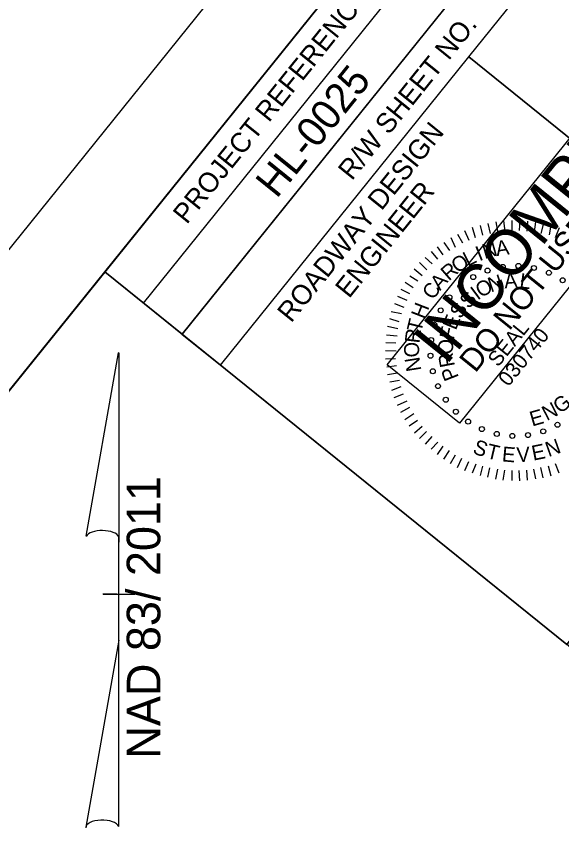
# Model space of a CAD drawing. Extents: x 1487832 to 1490056, y 498345 to 500343.
# Drawn here: x 1488790.9 to 1488928.7, y 500014.9 to 500224.6 of the extents above; entities that cross this region are included whole.
import ezdxf

# ---------------------------------------------------------------- set-up
doc = ezdxf.new("R2010")
doc.units = 0
for name, color, linetype in [('Old_Level_9', 7, 'Continuous'), ('Prop North Arrow NAD83 for Plan Sheets CELL', 7, 'Continuous'), ('Sheet Border Standard 30in CELL', 7, 'Continuous'), ('Sheet Clip Boundary CELL', 7, 'Continuous'), ('Sheet Data Field CELL', 7, 'Continuous'), ('Sheet Plan CELL', 7, 'Continuous'), ('Sheet Plot Border Outside CELL', 7, 'Continuous'), ('Sheet Sticker Incomplete CELL', 7, 'Continuous')]:
    doc.layers.add(name, color=color, linetype=linetype)

msp = doc.modelspace()

# ---------------------------------------------------------------- linework, layer by layer
at = {"layer": 'Old_Level_9'}
for p, q in [((1488910.12, 500172.28), (1488910.67, 500169.78)), ((1488912.13, 500172.71), (1488912.53, 500170.33)), ((1488914.02, 500172.98), (1488914.37, 500170.39)), ((1488916.15, 500173.07), (1488916.2, 500170.58)), ((1488918.21, 500173.07), (1488917.98, 500170.56)), ((1488920.15, 500172.93), (1488919.92, 500170.41)), ((1488922.16, 500172.72), (1488921.79, 500170.19)), ((1488924.19, 500172.36), (1488923.54, 500169.81)), ((1488904.19, 500170.51), (1488905.31, 500168.06)), ((1488906.16, 500171.36), (1488906.93, 500168.81)), ((1488908.18, 500171.79), (1488908.79, 500169.36)), ((1488926.01, 500171.92), (1488925.57, 500169.45)), ((1488928.15, 500171.22), (1488927.14, 500168.7)), ((1488900.75, 500168.79), (1488901.86, 500166.34)), ((1488902.44, 500169.61), (1488903.66, 500167.46)), ((1488897.3, 500166.43), (1488898.73, 500164.37)), ((1488898.96, 500167.53), (1488900.39, 500165.48)), ((1488895.8, 500165.2), (1488897.35, 500163.3)), ((1488892.82, 500162.46), (1488894.66, 500160.59)), ((1488894.25, 500163.75), (1488895.99, 500162.09)), ((1488891.5, 500160.83), (1488893.53, 500159.19)), ((1488890.34, 500159.07), (1488892.4, 500157.79)), ((1488888.14, 500155.7), (1488890.32, 500154.58)), ((1488889.23, 500157.52), (1488891.22, 500156.17)), ((1488887.26, 500153.97), (1488889.65, 500152.95)), ((1488886.53, 500152.11), (1488888.84, 500151.15)), ((1488885.68, 500150.1), (1488888.3, 500149.53)), ((1488885.24, 500148.28), (1488887.59, 500147.53)), ((1488884.73, 500146.37), (1488887.35, 500145.8)), ((1488884.47, 500144.14), (1488887.13, 500143.93)), ((1488884.32, 500142.21), (1488886.82, 500142.12)), ((1488884.25, 500140.21), (1488886.89, 500140.13)), ((1488884.26, 500138.15), (1488886.75, 500138.2)), ((1488884.55, 500136.11), (1488887, 500136.45)), ((1488884.76, 500134.15), (1488887.28, 500134.56)), ((1488885.32, 500132.29), (1488887.75, 500132.76)), ((1488885.82, 500130.21), (1488888.22, 500131.1)), ((1488886.38, 500128.35), (1488888.77, 500129.24)), ((1488887.23, 500126.37), (1488889.67, 500127.49)), ((1488888.13, 500124.62), (1488890.41, 500125.86)), ((1488889.11, 500122.81), (1488891.36, 500124.33)), ((1488890.21, 500121.15), (1488892.32, 500122.65)), ((1488891.53, 500119.44), (1488893.49, 500121.07)), ((1488892.82, 500118.01), (1488894.62, 500119.77)), ((1488894.33, 500116.54), (1488896.04, 500118.5)), ((1488895.74, 500115.27), (1488897.47, 500117.09)), ((1488897.38, 500113.95), (1488898.79, 500116.02)), ((1488899, 500112.77), (1488900.4, 500114.98)), ((1488900.68, 500111.67), (1488901.94, 500113.87)), ((1488902.43, 500110.65), (1488903.53, 500112.97)), ((1488904.28, 500109.92), (1488905.32, 500112.17)), ((1488906.2, 500109.28), (1488907.16, 500111.58)), ((1488928.11, 500109.21), (1488927.22, 500111.6)), ((1488908.26, 500108.64), (1488908.86, 500110.98)), ((1488910.09, 500108.2), (1488910.61, 500110.6)), ((1488912.13, 500107.71), (1488912.64, 500110.25)), ((1488914, 500107.48), (1488914.37, 500110.01)), ((1488916.22, 500107.36), (1488916.23, 500109.92)), ((1488918.22, 500107.29), (1488918.01, 500109.9)), ((1488920.12, 500107.43), (1488919.99, 500109.97)), ((1488922.22, 500107.79), (1488921.74, 500110.23)), ((1488924.11, 500108.07), (1488923.48, 500110.63)), ((1488926.13, 500108.5), (1488925.43, 500110.98))]:
    msp.add_line(p, q, dxfattribs=at)
for centre in [(1488913.87, 500161.35), (1488917.83, 500161.58), (1488910.02, 500160.41), (1488921.76, 500161.07), (1488925.53, 500159.85), (1488906.41, 500158.77), (1488929.02, 500157.96), (1488903.16, 500156.49), (1488900.38, 500153.66), (1488898.18, 500150.36), (1488896.61, 500146.72), (1488895.75, 500142.85), (1488895.6, 500138.89), (1488896.19, 500134.97), (1488897.49, 500131.22), (1488899.46, 500127.78), (1488902.02, 500124.75), (1488905.1, 500122.25), (1488927.71, 500121.44), (1488908.59, 500120.36), (1488924.1, 500119.8), (1488912.36, 500119.14), (1488916.29, 500118.63), (1488920.25, 500118.85)]:
    msp.add_circle(centre, 0.63, dxfattribs=at)
at = {"layer": 'Prop North Arrow NAD83 for Plan Sheets CELL'}
for p, q in [((1488808.52, 500093.27), (1488816.72, 500139.62)), ((1488816.77, 500139.62), (1488816.72, 500139.62)), ((1488816.77, 500139.62), (1488816.72, 500139.62)), ((1488816.77, 500139.62), (1488816.77, 500091.82)), ((1488816.77, 500067.02), (1488816.77, 500093.22)), ((1488816.77, 500091.82), (1488816.77, 500093.17)), ((1488812.77, 500078.62), (1488812.72, 500078.62)), ((1488816.32, 500078.62), (1488812.77, 500078.62)), ((1488812.82, 500078.62), (1488820.82, 500078.62)), ((1488816.77, 500067.02), (1488808.42, 500019.77)), ((1488816.82, 500019.97), (1488816.77, 500067.02))]:
    msp.add_line(p, q, dxfattribs=at)
for centre, start_param, end_param in [((1488812.65, 500092.77), 0.216388, 2.908219), ((1488812.65, 500019.6), 0.201328, 3.141593)]:
    msp.add_ellipse(centre, major_axis=(4.23, -0.03), ratio=0.461098, start_param=start_param, end_param=end_param, dxfattribs=at)
at = {"layer": 'Sheet Border Standard 30in CELL'}
msp.add_line((1488832.75, 500144.36), (1488842.48, 500136.51), dxfattribs=at)
at = {"layer": 'Sheet Clip Boundary CELL'}
msp.add_lwpolyline([(1488948.36, 500051.16), (1488813.25, 500160.1), (1488087.84, 499260.53), (1488879.09, 498569.08), (1489756.18, 499656.68), (1489073.94, 500206.87)], close=True, dxfattribs=at)
at = {"layer": 'Sheet Plan CELL'}
for p, q in [((1488823.01, 500152.21), (1488948.61, 500307.93)), ((1488832.78, 500144.35), (1488958.34, 500300.08)), ((1488832.78, 500144.35), (1488958.34, 500300.08)), ((1488905.31, 500214.39), (1488992.86, 500143.81)), ((1488832.78, 500144.35), (1488842.5, 500136.51))]:
    msp.add_line(p, q, dxfattribs=at)
for points in [[(1488938.86, 500315.83), (1487997.21, 499148.18), (1488814.55, 498489.05), (1489756.18, 499656.68)], [(1488813.25, 500160.1), (1488938.86, 500315.83), (1488958.34, 500300.08), (1488832.78, 500144.35)], [(1488905.31, 500214.39), (1488968.07, 500292.23), (1489055.66, 500221.61), (1488992.89, 500143.76)], [(1488814.55, 498489.05), (1487997.21, 499148.15), (1488813.25, 500160.1), (1488930.07, 500065.91), (1489055.66, 500221.61), (1489756.18, 499656.68)], [(1488842.5, 500136.51), (1488905.31, 500214.39), (1488992.89, 500143.76), (1488930.07, 500065.91)]]:
    msp.add_lwpolyline(points, close=True, dxfattribs=at)
at = {"layer": 'Sheet Plot Border Outside CELL'}
msp.add_lwpolyline([(1488727.56, 498345.32), (1489784.38, 499655.78), (1488932.01, 500343.17), (1487875.19, 499032.7)], close=True, dxfattribs=at)
at = {"layer": 'Sheet Sticker Incomplete CELL'}
msp.add_lwpolyline([(1488902.95, 500121.87), (1488884.66, 500136.62), (1488976.94, 500251.05), (1488995.23, 500236.3)], close=True, dxfattribs=at)

# ---------------------------------------------------------------- texts
at = {"layer": 'Old_Level_9'}
for s, height, rotation, p in [('A', 3.78, 8.1207, (1488912.35, 500164.05)), ('I', 3.78, 21.9216, (1488907.94, 500162.73)), ('N', 3.78, 16.0195, (1488909.3, 500163.3)), ('O', 3.78, 34.2024, (1488902.45, 500159.58)), ('L', 3.78, 26.8616, (1488905.03, 500161.35)), ('R', 3.78, 41.1372, (1488900.24, 500157.64)), ('A', 3.76, 5.0594, (1488914.36, 500155.88)), ('L', 3.76, 352.648, (1488917.97, 500156.05)), ('A', 3.78, 49.0905, (1488898.01, 500155.19)), ('O', 3.76, 28.9905, (1488908.29, 500153.45)), ('N', 3.76, 18.5087, (1488910.85, 500154.86)), ('C', 3.78, 56.0556, (1488896.34, 500152.81)), ('I', 3.76, 36.5977, (1488907.51, 500152.8)), ('S', 3.76, 44.1571, (1488905.19, 500150.56)), ('H', 3.78, 68.859, (1488894.09, 500147.95)), ('S', 3.76, 55.5837, (1488903.26, 500148)), ('E', 3.76, 67.7046, (1488902, 500145.17)), ('T', 3.78, 76.5514, (1488893.24, 500144.65)), ('R', 3.78, 83.2911, (1488892.82, 500141.91)), ('F', 3.76, 77.5156, (1488901.47, 500142.76)), ('SEAL', 3.759, 51.1156, (1488912.69, 500135.85)), ('030740', 3.759, 51.1156, (1488915.32, 500130.9)), ('O', 3.76, 89.3675, (1488901.29, 500139.19)), ('O', 3.78, 91.0599, (1488892.76, 500138.49)), ('R', 3.76, 100.8634, (1488901.81, 500136.33)), ('N', 3.78, 99.1823, (1488893.32, 500135.21)), ('P', 3.76, 111.2393, (1488902.83, 500133.45)), ('G', 3.76, 38.5969, (1488928.44, 500124.1)), ('N', 3.76, 27.174, (1488924.99, 500122.38)), ('E', 3.76, 15.9848, (1488921.3, 500120.99)), ('N', 3.78, 19.4446, (1488925.44, 500113.28)), ('S', 3.78, 339.3277, (1488906.03, 500114.36)), ('T', 3.78, 346.74, (1488909.52, 500113.07)), ('E', 3.78, 354.9381, (1488913.56, 500112.22)), ('V', 3.78, 3.0454, (1488917.45, 500111.98)), ('E', 3.78, 11.3469, (1488921.58, 500112.37))]:
    msp.add_text(s, height=height, rotation=rotation, dxfattribs=at).set_placement(p)
at = {"layer": 'Prop North Arrow NAD83 for Plan Sheets CELL'}
msp.add_text('NAD 83/ 2011', height=8.5, rotation=90, dxfattribs=at).set_placement((1488827.29, 500037.1))
at = {"layer": 'Sheet Data Field CELL'}
msp.add_text('HL-0025', height=7.5, rotation=51.1157, dxfattribs=at).set_placement((1488856.69, 500178.4))
at = {"layer": 'Sheet Plan CELL'}
for s, height, p in [('PROJECT REFERENCE NO.', 5.0001, (1488833.98, 500171.91)), ('R/W SHEET NO.', 5.0001, (1488875.72, 500182.95)), ('ROADWAY DESIGN', 5.0001, (1488860.35, 500147.01)), ('ENGINEER', 5, (1488875, 500153.17))]:
    msp.add_text(s, height=height, rotation=51.1157, dxfattribs=at).set_placement(p)
at = {"layer": 'Sheet Sticker Incomplete CELL'}
for s, height, p in [('INCOMPLETE PLANS', 11.52, (1488899.47, 500136.18)), ('DO NOT USE FOR R/W ACQUISITION', 5.76, (1488906.92, 500134.35))]:
    msp.add_text(s, height=height, rotation=51.1156, dxfattribs=at).set_placement(p)

doc.saveas('drawing.dxf')
